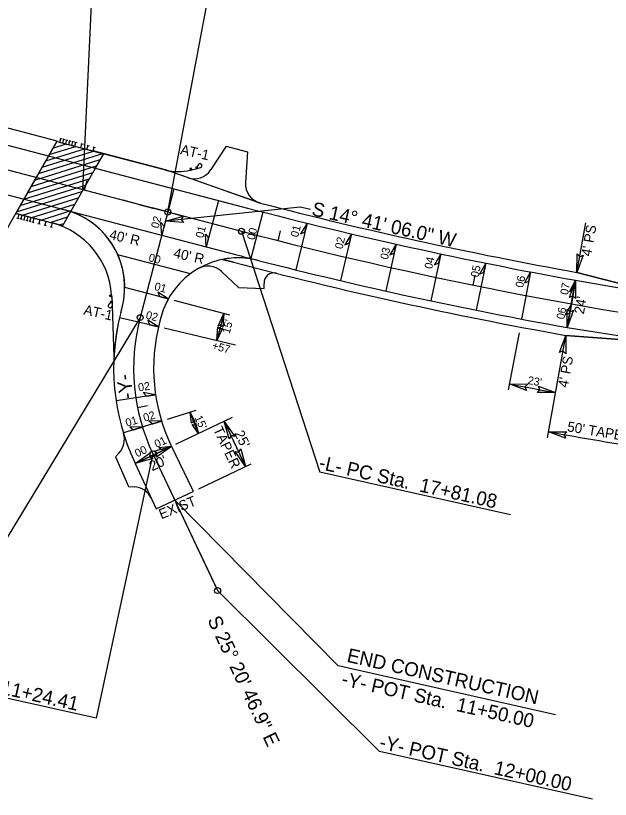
# Model space of a CAD drawing. Extents: x 1784740 to 1786163, y 841056 to 841833.
# Drawn here: x 1785617.7 to 1785915.1, y 841128.6 to 841520.3 of the extents above; entities that cross this region are included whole.
import ezdxf

# ---------------------------------------------------------------- set-up
doc = ezdxf.new("R2010")
doc.units = 0
for name, color, linetype in [('Old_Level_3', 7, 'Continuous'), ('Prop Approach Slab', 7, 'Continuous'), ('Prop Approach Slab Hatching', 7, 'Continuous'), ('Prop Dimension', 7, 'Continuous'), ('Prop DSN Text', 7, 'Continuous'), ('Prop EOT', 7, 'Continuous'), ('Prop Guardrail', 7, 'Continuous'), ('Prop Guardrail Anchor Unit CELL', 7, 'Continuous'), ('Prop Horizontal Alignment', 7, 'Continuous'), ('Prop Horizontal Alignment Direction Label', 7, 'Continuous'), ('Prop Horizontal Alignment Station Label', 7, 'Continuous'), ('Prop Horizontal Alignment Tick Large', 7, 'Continuous'), ('Prop Horizontal Alignment Tick Small', 7, 'Continuous'), ('Prop Lane Lines', 7, 'Continuous'), ('Prop Paved Shoulder', 7, 'Continuous'), ('Prop Roadway Bridge', 7, 'Continuous'), ('Prop Shade Light', 7, 'Continuous'), ('Prop Structure Anchor Unit CELL', 7, 'Continuous'), ('Prop Superelevation  Arrow CELL', 7, 'Continuous'), ('Prop Superelevation Label', 7, 'Continuous'), ('Prop Terminator CELL', 7, 'Continuous')]:
    doc.layers.add(name, color=color, linetype=linetype)

msp = doc.modelspace()

# ---------------------------------------------------------------- linework, layer by layer
at = {"layer": 'Old_Level_3'}
for p, q in [((1785722.94, 841455.04), (1785715.37, 841443.35)), ((1785722.94, 841455.04), (1785733.62, 841452.26)), ((1785733.62, 841452.26), (1785732.64, 841436.94)), ((1785729.2, 841384.4), (1785720.7, 841392.42)), ((1785729.2, 841384.4), (1785742.06, 841383.99)), ((1785742.06, 841383.99), (1785741.93, 841386.45)), ((1785667.71, 841299.84), (1785669.5, 841301.79)), ((1785667.71, 841299.84), (1785674.15, 841284.98)), ((1785674.15, 841284.98), (1785677, 841284.82))]:
    msp.add_line(p, q, dxfattribs=at)
for centre, radius, start, end in [((1785706.98, 841448.79), 10, 250.7541, 327.0873), ((1785742.62, 841436.31), 10, 176.3583, 255.4665), ((1785713.84, 841385.14), 10, 46.6792, 120.3956), ((1785746.92, 841386.71), 5, 75.9098, 182.9894), ((1785662.12, 841308.54), 10, 317.548, 17.2362), ((1785676.47, 841274.84), 10, 24.5527, 86.9232)]:
    msp.add_arc(centre, radius, start, end, dxfattribs=at)
at = {"layer": 'Prop Approach Slab'}
msp.add_lwpolyline([(1785638.3, 841457.44), (1785661.65, 841451.32), (1785641.14, 841415.34), (1785617.79, 841421.46)], close=True, dxfattribs=at)
at = {"layer": 'Prop Approach Slab Hatching'}
for p, q in [((1785634.58, 841450.92), (1785647.62, 841455)), ((1785636.4, 841454.11), (1785643.06, 841456.19)), ((1785643.05, 841456.03), (1785643.34, 841456.12)), ((1785629.13, 841441.36), (1785661.29, 841451.41)), ((1785630.95, 841444.55), (1785656.73, 841452.61)), ((1785632.77, 841447.73), (1785652.18, 841453.8)), ((1785627.31, 841438.17), (1785659.97, 841448.38)), ((1785625.5, 841434.98), (1785658.16, 841445.19)), ((1785621.86, 841428.61), (1785654.52, 841438.82)), ((1785623.68, 841431.8), (1785656.34, 841442.01)), ((1785620.05, 841425.42), (1785652.71, 841435.63)), ((1785618.23, 841422.23), (1785650.89, 841432.44)), ((1785621.24, 841420.56), (1785649.07, 841429.26)), ((1785625.8, 841419.36), (1785647.26, 841426.07)), ((1785630.36, 841418.17), (1785645.44, 841422.88)), ((1785634.92, 841416.97), (1785643.62, 841419.7)), ((1785639.47, 841415.78), (1785641.81, 841416.51))]:
    msp.add_line(p, q, dxfattribs=at)
at = {"layer": 'Prop Dimension'}
for p, q in [((1785898.4, 841392.02), (1785902.84, 841416.85)), ((1785893.48, 841364.46), (1785897.7, 841388.08)), ((1785883.63, 841309.33), (1785892.78, 841360.52)), ((1785725.94, 841319.39), (1785697.61, 841305.97)), ((1785722.04, 841317.54), (1785732.74, 841294.95)), ((1785722.51, 841316.54), (1785732.74, 841294.95)), ((1785677.57, 841296.48), (1785695.65, 841305.04)), ((1785709.26, 841283.82), (1785735.45, 841296.23))]:
    msp.add_line(p, q, dxfattribs=at)
msp.add_arc((1786269.36, 843468.14), 2190, 259.86941, 261.21755, dxfattribs=at)
at = {"layer": 'Prop DSN Text'}
for p, q in [((1785651.4, 841433.33), (1785665.25, 841730.55)), ((1785562.76, 841324.91), (1785628.04, 841439.45))]:
    msp.add_line(p, q, dxfattribs=at)
at = {"layer": 'Prop EOT'}
for p, q in [((1785396.43, 841512.55), (1785733.71, 841424.16)), ((1785390.34, 841489.34), (1785642.41, 841423.28)), ((1785897.7, 841388.08), (1785946.67, 841379.44)), ((1785670.32, 841371.99), (1785670.97, 841374.44)), ((1785690.32, 841369.41), (1785689.67, 841366.92)), ((1785893.48, 841364.46), (1785943.13, 841356.55)), ((1785695.39, 841305.57), (1785695.65, 841305.04)), ((1785677.32, 841297.01), (1785677.57, 841296.48)), ((1785677.57, 841296.48), (1785687.96, 841273.74)), ((1785687.96, 841273.74), (1785706.54, 841282.54))]:
    msp.add_line(p, q, dxfattribs=at)
for centre, radius, start, end in [((1785632.27, 841384.58), 40, 345.315, 75.315), ((1786269.36, 843468.14), 2113, 255.31501, 259.86941), ((1785729.02, 841359.27), 40, 75.6286, 165.315), ((1786269.36, 843468.14), 2137, 255.6286, 259.86941), ((1785776.73, 841344.1), 110, 165.315, 205.3464), ((1785776.73, 841344.1), 90, 165.315, 205.3464)]:
    msp.add_arc(centre, radius, start, end, dxfattribs=at)
msp.add_spline([(1785695.65, 841305.04), (1785695.79, 841304.74), (1785695.94, 841304.43), (1785696.09, 841304.13), (1785696.24, 841303.82), (1785696.38, 841303.52), (1785696.53, 841303.21), (1785696.68, 841302.91), (1785696.82, 841302.61), (1785696.97, 841302.3), (1785697.12, 841302), (1785697.27, 841301.69), (1785697.41, 841301.39), (1785697.56, 841301.09), (1785697.71, 841300.78), (1785697.86, 841300.48), (1785698, 841300.17), (1785698.15, 841299.87), (1785698.3, 841299.57), (1785698.44, 841299.26), (1785698.59, 841298.96), (1785698.74, 841298.65), (1785698.89, 841298.35), (1785699.03, 841298.05), (1785699.18, 841297.74), (1785699.33, 841297.44), (1785699.48, 841297.13), (1785699.62, 841296.83), (1785699.77, 841296.53), (1785699.92, 841296.22), (1785700.06, 841295.92), (1785700.21, 841295.61), (1785700.36, 841295.31), (1785700.51, 841295), (1785700.65, 841294.7), (1785700.8, 841294.4), (1785700.95, 841294.09), (1785701.1, 841293.79), (1785701.24, 841293.48), (1785701.39, 841293.18), (1785701.54, 841292.88), (1785701.68, 841292.57), (1785701.83, 841292.27), (1785701.98, 841291.96), (1785702.13, 841291.66), (1785702.27, 841291.36), (1785702.42, 841291.05), (1785702.57, 841290.75), (1785702.72, 841290.44), (1785702.86, 841290.14), (1785703.01, 841289.84), (1785703.16, 841289.53), (1785703.3, 841289.23), (1785703.45, 841288.92), (1785703.6, 841288.62), (1785703.75, 841288.32), (1785703.89, 841288.01), (1785704.04, 841287.71), (1785704.19, 841287.4), (1785704.33, 841287.1), (1785704.48, 841286.79), (1785704.63, 841286.49), (1785704.78, 841286.19), (1785704.92, 841285.88), (1785705.07, 841285.58), (1785705.22, 841285.27), (1785705.37, 841284.97), (1785705.51, 841284.67), (1785705.66, 841284.36), (1785705.81, 841284.06), (1785705.95, 841283.75), (1785706.1, 841283.45), (1785706.25, 841283.15), (1785706.54, 841282.54)], degree=3, dxfattribs=at)
at = {"layer": 'Prop Guardrail'}
msp.add_line((1785692.71, 841443.18), (1785656.44, 841452.68), dxfattribs=at)
for centre, radius, start, end in [((1785699.05, 841467.36), 25, 255.315, 283.9629), ((1785625.79, 841378.01), 40, 3.6953, 75.315)]:
    msp.add_arc(centre, radius, start, end, dxfattribs=at)
at = {"layer": 'Prop Guardrail Anchor Unit CELL'}
for p, q in [((1785705.56, 841444.05), (1785704.89, 841443.88)), ((1785704.89, 841443.88), (1785705.08, 841443.1)), ((1785705.76, 841443.27), (1785704.89, 841443.88)), ((1785705.08, 841443.1), (1785705.56, 841444.05)), ((1785705.08, 841443.1), (1785708.52, 841443.96)), ((1785705.08, 841443.1), (1785705.76, 841443.27)), ((1785705.76, 841443.27), (1785705.56, 841444.05)), ((1785708.52, 841444.79), (1785707.84, 841444.62)), ((1785707.84, 841444.62), (1785708.03, 841443.83)), ((1785708.71, 841444), (1785707.84, 841444.62)), ((1785708.03, 841443.83), (1785708.52, 841444.79)), ((1785708.03, 841443.83), (1785708.71, 841444)), ((1785708.58, 841443.97), (1785708.46, 841443.94)), ((1785708.58, 841443.97), (1785708.46, 841443.94)), ((1785708.71, 841444), (1785708.52, 841444.79)), ((1785708.52, 841443.96), (1785710.19, 841444.37)), ((1785709.03, 841445.72), (1785708.56, 841444.6)), ((1785708.71, 841444), (1785708.63, 841444.35)), ((1785708.71, 841444), (1785708.63, 841444.35)), ((1785664.9, 841380.54), (1785665.7, 841380.59)), ((1785664.94, 841379.84), (1785664.9, 841380.54)), ((1785665.75, 841379.89), (1785664.9, 841380.54)), ((1785665.7, 841380.59), (1785664.94, 841379.84)), ((1785665.7, 841380.59), (1785665.93, 841377.06)), ((1785665.7, 841380.59), (1785665.75, 841379.89)), ((1785664.41, 841376.03), (1785665.24, 841376.75)), ((1785665.75, 841379.89), (1785664.94, 841379.84)), ((1785665.1, 841377.44), (1785665.9, 841377.49)), ((1785665.14, 841376.74), (1785665.1, 841377.44)), ((1785665.95, 841376.79), (1785665.1, 841377.44)), ((1785665.9, 841377.49), (1785665.14, 841376.74)), ((1785665.95, 841376.79), (1785665.14, 841376.74)), ((1785665.95, 841376.79), (1785665.6, 841376.77)), ((1785665.95, 841376.79), (1785665.6, 841376.77)), ((1785665.9, 841377.49), (1785665.95, 841376.79)), ((1785665.94, 841376.92), (1785665.93, 841377.06)), ((1785665.93, 841377.06), (1785666.04, 841375.34)), ((1785665.94, 841376.92), (1785665.93, 841377.06))]:
    msp.add_line(p, q, dxfattribs=at)
for centre, major_axis, start_param, end_param in [((1785709.95, 841445.33), (-0.24, 0.964), 3.141593, 7.214552), ((1785665.05, 841375.28), (0.991, 0.064), 2.210226, 6.283185)]:
    msp.add_ellipse(centre, major_axis=major_axis, ratio=0.995379, start_param=start_param, end_param=end_param, dxfattribs=at)
at = {"layer": 'Prop Horizontal Alignment'}
for p, q in [((1785393.39, 841500.94), (1785730.66, 841412.56)), ((1785693.82, 841422.21), (1785680, 841369.45)), ((1785686.36, 841301.29), (1785718.14, 841234.2)), ((1785686.36, 841301.29), (1785718.72, 841232.97))]:
    msp.add_line(p, q, dxfattribs=at)
for centre, radius, start, end in [((1786269.36, 843468.14), 2125, 255.31501, 262.56569), ((1785776.73, 841344.1), 100, 165.315, 205.3464)]:
    msp.add_arc(centre, radius, start, end, dxfattribs=at)
at = {"layer": 'Prop Horizontal Alignment Direction Label'}
for p, q in [((1785759.99, 841424.58), (1785692.61, 841417.59)), ((1785765.17, 841423.42), (1785759.99, 841424.58))]:
    msp.add_line(p, q, dxfattribs=at)
at = {"layer": 'Prop Horizontal Alignment Station Label'}
for p, q in [((1785693.82, 841422.21), (1785741.97, 841678.56)), ((1785730.66, 841412.56), (1785769.82, 841292.18)), ((1785680, 841369.45), (1785582.83, 841208.91)), ((1785686.36, 841301.29), (1785658, 841169.14)), ((1785865.24, 841270.78), (1785769.82, 841292.18)), ((1785778.97, 841195.28), (1785697.31, 841278.16)), ((1785718.72, 841232.97), (1785799.6, 841152.5)), ((1785887.66, 841170.91), (1785778.97, 841195.28)), ((1785658, 841169.14), (1785557.09, 841191.77)), ((1785906.13, 841128.61), (1785799.6, 841152.5))]:
    msp.add_line(p, q, dxfattribs=at)
for centre in [(1785693.82, 841422.21), (1785730.66, 841412.56), (1785680, 841369.45), (1785686.36, 841301.29), (1785718.72, 841232.97)]:
    msp.add_circle(centre, 1.5, dxfattribs=at)
at = {"layer": 'Prop Horizontal Alignment Tick Large'}
for p, q in [((1785679.31, 841426.01), (1785671.57, 841428.04)), ((1785679.31, 841426.01), (1785687.05, 841423.99)), ((1785693.82, 841422.21), (1785686.08, 841424.24)), ((1785693.82, 841422.21), (1785701.56, 841420.18))]:
    msp.add_line(p, q, dxfattribs=at)
at = {"layer": 'Prop Horizontal Alignment Tick Small'}
for p, q in [((1785652.23, 841433.11), (1785653.49, 841437.95)), ((1785748.98, 841407.84), (1785750.21, 841412.69)), ((1785846.48, 841385.64), (1785847.47, 841390.54)), ((1785678.69, 841324.4), (1785683.59, 841325.39))]:
    msp.add_line(p, q, dxfattribs=at)
at = {"layer": 'Prop Lane Lines'}
msp.add_line((1785642.41, 841423.28), (1785727.62, 841400.95), dxfattribs=at)
msp.add_arc((1786269.36, 843468.14), 2137, 255.31501, 255.6286, dxfattribs=at)
at = {"layer": 'Prop Paved Shoulder'}
for p, q in [((1785660.61, 841451.59), (1785692.71, 841443.18)), ((1785740.11, 841426.63), (1785692.71, 841443.18)), ((1785721.21, 841398.5), (1785726.61, 841397.08)), ((1785898.4, 841392.02), (1785946.67, 841379.44)), ((1785665.7, 841380.59), (1785666.04, 841375.34)), ((1785666.04, 841375.34), (1785666.88, 841349.79)), ((1785892.78, 841360.52), (1785943.13, 841356.55))]:
    msp.add_line(p, q, dxfattribs=at)
for centre, radius, start, end in [((1786269.36, 843468.14), 2109, 255.46645, 259.86941), ((1785625.79, 841378.01), 40, 3.6953, 75.315), ((1786269.36, 843468.14), 2141, 255.31501, 259.86941)]:
    msp.add_arc(centre, radius, start, end, dxfattribs=at)
at = {"layer": 'Prop Roadway Bridge'}
for p, q in [((1785454.59, 841505.93), (1785638.38, 841457.76)), ((1785638.3, 841457.44), (1785617.79, 841421.46))]:
    msp.add_line(p, q, dxfattribs=at)
at = {"layer": 'Prop Shade Light'}
for p, q in [((1785692.71, 841443.18), (1785661.65, 841451.32)), ((1785726.61, 841397.08), (1785721.21, 841398.5)), ((1785946.67, 841379.44), (1785898.4, 841392.02)), ((1785897.7, 841388.08), (1785946.67, 841379.44)), ((1785665.7, 841380.59), (1785666.04, 841375.34)), ((1785666.04, 841375.34), (1785666.88, 841349.79)), ((1785670.32, 841371.99), (1785670.97, 841374.44)), ((1785893.48, 841364.46), (1785943.13, 841356.55)), ((1785943.13, 841356.55), (1785892.78, 841360.52))]:
    msp.add_line(p, q, dxfattribs=at)
for points in [[(1785661.65, 841451.32), (1785659.97, 841448.38), (1785658.16, 841445.19), (1785657.55, 841444.12)], [(1785657.55, 841444.12), (1785696.86, 841433.82), (1785719.11, 841427.99), (1785733.71, 841424.16)], [(1785738.56, 841427.17), (1785703.68, 841439.35), (1785692.71, 841443.18)], [(1785645.19, 841422.44), (1785643.62, 841419.7), (1785641.81, 841416.51), (1785641.14, 841415.34), (1785639.47, 841415.78), (1785635.93, 841416.71)]]:
    msp.add_lwpolyline(points, dxfattribs=at)
for centre, radius, start, end in [((1785742.62, 841436.31), 10, 246.0417, 255.4665), ((1786269.36, 843468.14), 2113, 255.31501, 259.86941), ((1786269.36, 843468.14), 2109, 255.46645, 259.86941), ((1785632.27, 841384.58), 40, 345.315, 71.1625), ((1785625.79, 841378.01), 40, 3.6953, 75.315), ((1785729.02, 841359.27), 40, 75.6286, 101.2549), ((1786269.36, 843468.14), 2141, 255.31501, 259.86941), ((1786269.36, 843468.14), 2137, 255.6286, 259.86941), ((1785776.73, 841344.1), 110, 165.315, 177.0376)]:
    msp.add_arc(centre, radius, start, end, dxfattribs=at)
at = {"layer": 'Prop Structure Anchor Unit CELL'}
for p, q in [((1785639.76, 841459.12), (1785640.87, 841458.83)), ((1785639.81, 841457.04), (1785640.32, 841458.98)), ((1785641.27, 841458.73), (1785642.38, 841458.43)), ((1785641.32, 841456.65), (1785641.83, 841458.58)), ((1785642.79, 841458.33), (1785643.89, 841458.04)), ((1785638.3, 841457.44), (1785656.44, 841452.68)), ((1785642.83, 841456.25), (1785643.34, 841458.18)), ((1785644.3, 841457.93), (1785645.4, 841457.64)), ((1785644.34, 841455.85), (1785644.85, 841457.79)), ((1785645.81, 841457.54), (1785646.92, 841457.25)), ((1785645.86, 841455.46), (1785646.36, 841457.39)), ((1785647.32, 841457.14), (1785648.43, 841456.85)), ((1785647.37, 841455.06), (1785647.87, 841457)), ((1785650.34, 841456.35), (1785651.45, 841456.06)), ((1785650.39, 841454.27), (1785650.9, 841456.2)), ((1785653.37, 841455.56), (1785654.47, 841455.27)), ((1785653.41, 841453.48), (1785653.92, 841455.41)), ((1785656.39, 841454.76), (1785657.5, 841454.47)), ((1785656.44, 841452.68), (1785656.94, 841454.62)), ((1785617.79, 841421.46), (1785635.93, 841416.71)), ((1785618.24, 841419.28), (1785619.35, 841418.99)), ((1785619.3, 841421.07), (1785618.79, 841419.13)), ((1785620.81, 841420.67), (1785620.31, 841418.73)), ((1785622.32, 841420.27), (1785621.82, 841418.34)), ((1785623.84, 841419.88), (1785623.33, 841417.94)), ((1785625.35, 841419.48), (1785624.84, 841417.55)), ((1785619.75, 841418.88), (1785620.86, 841418.59)), ((1785621.26, 841418.48), (1785622.37, 841418.19)), ((1785622.77, 841418.09), (1785623.88, 841417.8)), ((1785624.29, 841417.69), (1785625.39, 841417.4)), ((1785625.8, 841417.3), (1785626.91, 841417)), ((1785626.86, 841419.08), (1785626.35, 841417.15)), ((1785628.82, 841416.5), (1785629.93, 841416.21)), ((1785629.88, 841418.29), (1785629.37, 841416.36)), ((1785631.84, 841415.71), (1785632.95, 841415.42)), ((1785632.9, 841417.5), (1785632.4, 841415.57)), ((1785635.93, 841416.71), (1785635.42, 841414.77)), ((1785634.87, 841414.92), (1785635.97, 841414.63))]:
    msp.add_line(p, q, dxfattribs=at)
at = {"layer": 'Prop Superelevation  Arrow CELL'}
for points in [[(1785690.78, 841410.6), (1785690.37, 841416.91), (1785691.95, 841415.08)], [(1785763.5, 841416.59), (1785760.12, 841411.24), (1785762.39, 841412.1)], [(1785713.03, 841404.77), (1785712.62, 841411.08), (1785714.2, 841409.25)], [(1785785.73, 841411.23), (1785782.41, 841405.85), (1785784.67, 841406.73)], [(1785808.02, 841406.12), (1785804.76, 841400.7), (1785807.01, 841401.61)], [(1785830.37, 841401.25), (1785827.16, 841395.79), (1785829.41, 841396.72)], [(1785852.76, 841396.62), (1785849.62, 841391.13), (1785851.85, 841392.08)], [(1785875.21, 841392.23), (1785872.12, 841386.71), (1785874.35, 841387.69)], [(1785897.7, 841388.08), (1785894.68, 841382.53), (1785896.89, 841383.53)], [(1785694.07, 841378.73), (1785688.77, 841382.18), (1785689.6, 841379.9)], [(1785895.59, 841376.27), (1785892.57, 841370.72), (1785894.78, 841371.72)], [(1785689.13, 841364.77), (1785683.75, 841368.09), (1785684.63, 841365.83)], [(1785687.72, 841330.8), (1785681.49, 841331.9), (1785683.14, 841330.12)], [(1785690.7, 841317.65), (1785684.38, 841317.8), (1785686.28, 841316.29)], [(1785681.15, 841314.71), (1785674.82, 841314.86), (1785676.73, 841313.35)], [(1785695.65, 841305.04), (1785689.37, 841304.28), (1785691.47, 841303.06)]]:
    msp.add_lwpolyline(points, close=True, dxfattribs=at)
at = {"layer": 'Prop Superelevation Label'}
for p, q in [((1785696.86, 841433.82), (1785690.78, 841410.6)), ((1785719.11, 841427.99), (1785713.03, 841404.77)), ((1785741.32, 841422.18), (1785735.32, 841398.94)), ((1785763.5, 841416.59), (1785757.75, 841393.29)), ((1785785.73, 841411.23), (1785780.24, 841387.87)), ((1785808.02, 841406.12), (1785802.78, 841382.7)), ((1785705.11, 841391.34), (1785668.82, 841400.85)), ((1785830.37, 841401.25), (1785825.38, 841377.77)), ((1785852.76, 841396.62), (1785848.03, 841373.09)), ((1785875.21, 841392.23), (1785870.73, 841368.65)), ((1785897.7, 841388.08), (1785895.59, 841376.27)), ((1785694.07, 841378.73), (1785672.27, 841384.44)), ((1785724.77, 841370.68), (1785696.97, 841377.97)), ((1785895.59, 841376.27), (1785893.48, 841364.46)), ((1785689.13, 841364.77), (1785669.67, 841369.36)), ((1785721.87, 841371.44), (1785718.32, 841357.88)), ((1785727.72, 841355.67), (1785692.05, 841364.08)), ((1785869.43, 841361.77), (1785864.02, 841333.28)), ((1785687.72, 841330.8), (1785667.94, 841327.85)), ((1785707.91, 841322.94), (1785693.57, 841318.53)), ((1785690.7, 841317.65), (1785671.59, 841311.77)), ((1785695.65, 841305.04), (1785677.57, 841296.48))]:
    msp.add_line(p, q, dxfattribs=at)
for centre, radius, start, end in [((1786269.36, 843468.14), 2170, 259.24927, 259.86941), ((1785776.73, 841344.1), 75, 197.0911, 205.7986)]:
    msp.add_arc(centre, radius, start, end, dxfattribs=at)
at = {"layer": 'Prop Terminator CELL'}
for points in [[(1785701.72, 841416.98), (1785692.61, 841417.59), (1785701.45, 841420.12), (1785700.47, 841418.41)], [(1785901.51, 841400.61), (1785898.4, 841392.02), (1785898.42, 841401.21), (1785899.79, 841399.8)], [(1785894.59, 841379.5), (1785897.7, 841388.08), (1785897.68, 841378.89), (1785896.31, 841380.31)], [(1785896.59, 841373.05), (1785893.48, 841364.46), (1785893.5, 841373.65), (1785894.87, 841372.24)], [(1785719.03, 841365.21), (1785721.87, 841371.44), (1785721.31, 841364.57), (1785720.37, 841365.71)], [(1785721.15, 841364.12), (1785718.32, 841357.88), (1785718.88, 841364.75), (1785719.82, 841363.62)], [(1785889.67, 841351.93), (1785892.78, 841360.52), (1785892.76, 841351.33), (1785891.39, 841352.74)], [(1785873.13, 841333.03), (1785864.58, 841336.23), (1785873.77, 841336.11), (1785872.34, 841334.76)], [(1785879.09, 841335.08), (1785887.67, 841331.97), (1785878.48, 841331.99), (1785879.9, 841333.36)], [(1785705.74, 841316.63), (1785705.04, 841322.06), (1785707.56, 841317.15), (1785706.43, 841317.53)], [(1785724.49, 841308.74), (1785722.04, 841317.54), (1785727.36, 841310.05), (1785725.42, 841310.4)], [(1785707.69, 841316.73), (1785709.2, 841311.46), (1785705.98, 841315.93), (1785707.14, 841315.73)], [(1785892.74, 841309.18), (1785884.16, 841312.28), (1785893.35, 841312.27), (1785891.93, 841310.9)], [(1785686.37, 841298.93), (1785677.57, 841296.48), (1785685.07, 841301.8), (1785684.71, 841299.86)], [(1785686.85, 841302.59), (1785695.65, 841305.04), (1785688.15, 841299.72), (1785688.51, 841301.66)], [(1785730.29, 841303.74), (1785732.74, 841294.95), (1785727.42, 841302.44), (1785729.36, 841302.09)]]:
    msp.add_lwpolyline(points, close=True, dxfattribs=at)

# ---------------------------------------------------------------- texts
at = {"layer": 'Prop Dimension'}
for s, rotation, p in [("4' PS", 79.8694, (1785905.39, 841399.75)), ("40' R", 347.3599, (1785664.26, 841408.65)), ("40' R", 347.3599, (1785696.35, 841399.5)), ("24'", 79.8694, (1785901.82, 841370.89)), ("4' PS", 79.8694, (1785893.77, 841334.15)), ("50' TAPER", 350.482, (1785893.26, 841312.62)), ('TAPER', 295.3464, (1785716.34, 841313.55)), ("25'", 295.3464, (1785726.94, 841311.61)), ("20'", 25.3464, (1785686.01, 841292.54)), ('EXIST', 22.0324, (1785690.57, 841268.56))]:
    msp.add_text(s, height=5, rotation=rotation, dxfattribs=at).set_placement(p)
at = {"layer": 'Prop Guardrail Anchor Unit CELL'}
for p in [(1785699.77, 841451.17), (1785651.44, 841371.07)]:
    msp.add_text('AT-1', height=5, rotation=347.3599, dxfattribs=at).set_placement(p)
at = {"layer": 'Prop Horizontal Alignment Direction Label'}
for s, rotation, p in [('S 14%%d 41\' 06.0" W', 347.3599, (1785765.39, 841420.59)), ('-Y-', 98.1429, (1785676.77, 841329.2)), ('S 25%%d 20\' 46.9" E', 295.3464, (1785713.47, 841218.28))]:
    msp.add_text(s, height=7, rotation=rotation, dxfattribs=at).set_placement(p)
at = {"layer": 'Prop Horizontal Alignment Station Label'}
for s, p in [('-L- PC Sta.  17+81.08', (1785768.98, 841293.81)), ('END CONSTRUCTION', (1785782.95, 841197.41)), ('-Y- PT Sta.  11+24.41', (1785559.75, 841192.67)), ('-Y- POT Sta.  11+50.00', (1785780.32, 841185.7)), ('-Y- POT Sta.  12+00.00', (1785799.18, 841154.1))]:
    msp.add_text(s, height=7, rotation=347.3599, dxfattribs=at).set_placement(p)
at = {"layer": 'Prop Superelevation Label'}
for s, rotation, p in [('02', 75.315, (1785689.18, 841413.74)), ('01', 75.315, (1785711.43, 841408.88)), ('00', 75.5284, (1785737.14, 841407.92)), ('01', 76.1486, (1785758.95, 841409.32)), ('02', 76.7687, (1785781.12, 841403.39)), ('03', 77.3888, (1785803.81, 841398.19)), ('00', 345.315, (1785683.94, 841397.68)), ('04', 78.009, (1785825.95, 841393.47)), ('05', 78.6291, (1785849.12, 841389.29)), ('06', 79.2493, (1785871.5, 841384.12)), ('01', 345.315, (1785686.81, 841383.27)), ('07', 79.8694, (1785893.89, 841380.54)), ('02', 345.315, (1785682.52, 841368.97)), ('06', 79.8694, (1785892.03, 841368.32)), ("15'", 75.315, (1785724.72, 841361.05)), ('+57', 345.315, (1785715.64, 841353.7)), ('02', 8.4968, (1785679.27, 841332.49)), ("23'", 349.5428, (1785873.52, 841336.27)), ('02', 17.0911, (1785682.23, 841317.3)), ('01', 17.0911, (1785673.34, 841314.78)), ("15'", 294.4935, (1785707.08, 841319.45)), ('01', 25.3464, (1785688.25, 841304.1)), ('00', 25.3464, (1785678.47, 841299.46))]:
    msp.add_text(s, height=4, rotation=rotation, dxfattribs=at).set_placement(p)

doc.saveas('drawing.dxf')
